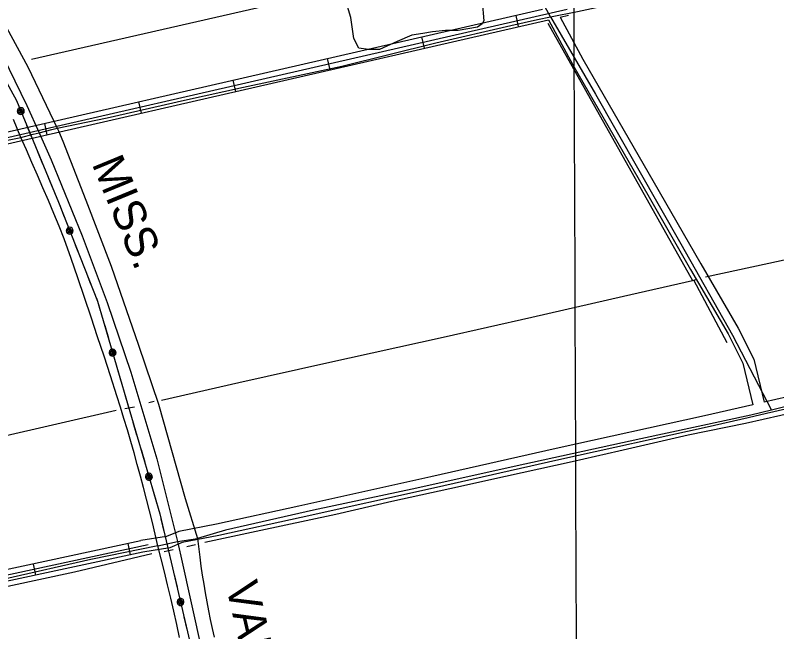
# Model space of a CAD drawing. Extents: x 3392644 to 3430565, y 576657 to 602123.
# Drawn here: x 3416383 to 3418352, y 588816 to 590409 of the extents above; entities that cross this region are included whole.
import ezdxf

# ---------------------------------------------------------------- set-up
doc = ezdxf.new("R2010")
doc.units = 0
for name, color, linetype in [('V-DTCH-CNTR', 7, 'Continuous'), ('V-GRID-MAJR', 7, 'Continuous'), ('V-RAIL-IDEN', 7, 'Continuous'), ('V-RAIL-TRAK', 7, 'Continuous'), ('V-ROAD-CNTR', 7, 'Continuous'), ('V-SITE-VEGE', 7, 'Continuous'), ('V-TOPO-SHOR', 7, 'Continuous'), ('V-UTIL-LINE', 7, 'Continuous')]:
    doc.layers.add(name, color=color, linetype=linetype)

msp = doc.modelspace()

# ---------------------------------------------------------------- linework, layer by layer
at = {"layer": 'V-DTCH-CNTR'}
for p, q in [((3416751.924, 589038.157), (3416802.573, 589049.001)), ((3416802.573, 589049.001), (3416854.21, 589057.238))]:
    msp.add_line(p, q, dxfattribs=at)
for points in [[(3416491.605, 590116.775), (3416620.816, 590143.532), (3416820.876, 590189.567), (3416973.508, 590222.931), (3417227.964, 590276.8470000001), (3417470.289, 590337.596), (3417664.788, 590381.71), (3417732.961, 590397.492), (3417766.504, 590404.1460000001), (3417837.039, 590418.138), (3418032.7090000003, 590461.1730000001), (3418235.963, 590511.853), (3418401.431, 590548.5650000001), (3418685.449, 590610.2000000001), (3418902.3880000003, 590657.762), (3419134.879, 590710.775), (3419369.647, 590763.316), (3419640.039, 590827.478), (3419543.482, 591021.51), (3419461.076, 591173.248), (3419330.748, 591406.505), (3419213.62, 591620.562), (3419101.41, 591830.308), (3419067.453, 591901.898)], [(3417766.504, 590404.1460000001), (3417681.237, 590559.925), (3417675.611, 590570.204), (3417541.109, 590808.931), (3417406.021, 591048.197), (3417273.464, 591280.797), (3417162.495, 591479.537), (3417026.426, 591721.203)], [(3416321.316, 590449.546), (3416415.936, 590275.182), (3416491.605, 590116.775), (3416494.9560000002, 590109.763), (3416506.207, 590083.149), (3416566.062, 589931.044), (3416631.211, 589759.976), (3416701.648, 589556.407), (3416753.62, 589403.979), (3416822.324, 589160.287), (3416854.21, 589057.238), (3416860.169, 589008.403), (3416863.458, 588985.302), (3416866.961, 588962.231), (3416870.676, 588939.193), (3416874.606, 588916.1900000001), (3416878.7490000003, 588893.226), (3416883.107, 588870.299), (3416887.674, 588847.414), (3416892.4560000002, 588824.5750000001), (3416897.449, 588801.779)], [(3417766.504, 590404.1460000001), (3417883.0100000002, 590204.818), (3418103.721, 589817.894), (3418236.98, 589581.938), (3418338.123, 589388.713)], [(3416808.378, 588801.046), (3416800.884, 588835.053), (3416793.198, 588869.017), (3416785.323, 588902.936), (3416777.258, 588936.812), (3416769.003, 588970.64), (3416760.559, 589004.422), (3416751.924, 589038.157), (3416744.9590000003, 589068.283), (3416737.793, 589098.3640000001), (3416730.427, 589128.394), (3416722.855, 589158.376), (3416715.085, 589188.306), (3416707.11, 589218.184), (3416698.9390000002, 589248.007), (3416690.5640000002, 589277.775), (3416681.989, 589307.487), (3416673.218, 589337.138), (3416664.2430000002, 589366.734), (3416655.072, 589396.2660000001), (3416645.705, 589425.735), (3416629.505, 589476.623), (3416613.086, 589527.442), (3416596.448, 589578.1900000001), (3416579.593, 589628.866), (3416562.519, 589679.468), (3416545.228, 589729.996), (3416527.718, 589780.448), (3416509.99, 589830.8250000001), (3416496.5470000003, 589863.853), (3416482.932, 589896.814), (3416469.145, 589929.7000000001), (3416455.186, 589962.515), (3416441.056, 589995.257), (3416426.757, 590027.925), (3416412.288, 590060.5160000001), (3416397.651, 590093.03), (3416388.234, 590115.9720000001), (3416378.6210000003, 590138.834)], [(3416220.878, 590052.077), (3416363.771, 590086.149), (3416397.667, 590092.992), (3416429.799, 590101.3250000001), (3416444.896, 590104.444), (3416477.7090000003, 590113.465), (3416491.605, 590116.775)], [(3419032.2430000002, 589545.584), (3418761.35, 589487.1950000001), (3418572.0500000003, 589446.526), (3418338.123, 589388.713), (3418284.453, 589375.4500000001), (3418000.406, 589314.11), (3417673.34, 589242.537), (3417421.772, 589187.046), (3417153.916, 589129.758), (3416927.0100000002, 589078.103), (3416854.21, 589057.238)], [(3416751.924, 589038.157), (3416579.065, 589002.831), (3416358.87, 588952.581), (3416176.576, 588913.485)]]:
    msp.add_lwpolyline(points, dxfattribs=at)
at = {"layer": 'V-GRID-MAJR'}
msp.add_spline([(3417859.292, 582120.98), (3417836.383, 588179.004), (3417813.4620000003, 594240.1140000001), (3417790.541, 600301.242), (3417790.529, 600304.306)], degree=3, dxfattribs=at)
at = {"layer": 'V-RAIL-TRAK'}
msp.add_lwpolyline([(3416192.597, 590596.707), (3416262.3540000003, 590474.978), (3416336.012, 590332.644), (3416413.347, 590175.192), (3416444.896, 590104.444), (3416475.932, 590034.8470000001), (3416556.703, 589838.446), (3416621.203, 589666.416), (3416682.344, 589486.919), (3416749.61, 589262.476), (3416802.573, 589049.001), (3416811.861, 589011.564), (3416866.719, 588762.179), (3416909.6350000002, 588565.4400000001), (3416972.856, 588276.088), (3417019.418, 588058.134), (3417070.958, 587822.036), (3417121.963, 587592.037), (3417123.169, 587586.438)], dxfattribs=at)
at = {"layer": 'V-ROAD-CNTR'}
for p, q in [((3417677.03260815, 590408.3251568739), (3417683.7365947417, 590379.0842153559)), ((3417433.3540955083, 590352.4602686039), (3417440.0580821, 590323.219327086)), ((3417189.676582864, 590296.596380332), (3417196.380569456, 590267.3544388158)), ((3416945.99907022, 590240.7314920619), (3416952.7020568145, 590211.490550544)), ((3416702.320557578, 590184.8676037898), (3416709.0245441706, 590155.6256622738)), ((3416458.643044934, 590129.0027155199), (3416465.3470315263, 590099.7617740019)), ((3416681.501599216, 589014.9209436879), (3416675.206611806, 589044.2528850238)), ((3416437.0700880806, 588962.45504862), (3416430.774100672, 588991.7869899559))]:
    msp.add_line(p, q, dxfattribs=at)
for points in [[(3417810.229341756, 590423.47212658), (3415682.2255977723, 589935.616102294)], [(3415687.339587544, 589952.17806917), (3417746.240469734, 590424.19212514)], [(3417791.6993788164, 590403.8341658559), (3417813.581335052, 590408.8511558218)], [(3417791.6993788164, 590403.8341658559), (3417850.6062610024, 590294.87238378), (3418048.1718658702, 589953.5170664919), (3418155.1476519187, 589766.3204408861), (3418252.269457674, 589599.964773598), (3418292.390377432, 589520.5039325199), (3418319.0123241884, 589408.803155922)], [(3415700.975560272, 589924.525124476), (3417761.3574395, 590396.8781797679)], [(3417761.3574395, 590396.8781797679), (3417824.42231337, 590280.22241308), (3418022.165917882, 589938.5610964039), (3418129.1697038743, 589751.3144708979), (3418225.9015104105, 589585.6288022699), (3418264.024434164, 589510.12395328), (3418289.7643826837, 589402.1241692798)], [(3418902.30015761, 589544.065885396), (3418797.492367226, 589520.04893343), (3418789.1113839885, 589518.952935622), (3418680.741600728, 589491.412990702), (3418319.0123241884, 589408.803155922)], [(3418918.49512522, 589516.9979395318), (3418802.80035661, 589490.4869925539), (3418794.7713726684, 589489.436994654), (3418687.777586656, 589462.2470490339), (3418325.3783114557, 589379.48421456)], [(3418289.7643826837, 589402.1241692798), (3418164.799632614, 589373.5852263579)], [(3418325.3783114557, 589379.48421456), (3418277.7164067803, 589368.59923633)], [(3418164.799632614, 589373.5852263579), (3417781.8403985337, 589288.9463956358), (3417457.867046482, 589216.383540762), (3417116.151729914, 589140.617692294), (3416903.753154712, 589094.1287852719), (3416806.330349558, 589075.053823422), (3416774.8074126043, 589061.9258496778), (3416707.925546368, 589051.2758709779)], [(3418277.7164067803, 589368.59923633), (3418171.4796192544, 589344.3372848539)], [(3418171.4796192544, 589344.3372848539), (3417788.2223857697, 589259.632454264), (3417464.39303343, 589187.1015993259), (3417122.6057170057, 589111.31975089), (3416909.8431425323, 589064.750844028), (3416815.0683320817, 589046.1958811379), (3416783.047396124, 589032.85990781), (3416713.4845352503, 589021.7859299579)], [(3416154.961652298, 588932.5911083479), (3416707.925546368, 589051.2758709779)], [(3416727.240507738, 589040.0798933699), (3416026.868908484, 588889.7501940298), (3415908.3611455, 588864.4192446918), (3415874.654212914, 588843.9242856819)], [(3416713.4845352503, 589021.7859299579), (3416158.6886309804, 588902.7029736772)]]:
    msp.add_lwpolyline(points, dxfattribs=at)
at = {"layer": 'V-SITE-VEGE'}
msp.add_lwpolyline([(3417590.6210000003, 590444.201), (3417594.771, 590394.385), (3417590.6210000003, 590386.083), (3417578.18, 590377.778), (3417528.401, 590369.478), (3417495.215, 590369.478), (3417462.029, 590365.324), (3417437.14, 590361.1730000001), (3417408.1040000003, 590357.024), (3417370.771, 590340.417), (3417325.1410000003, 590319.66), (3417296.105, 590319.66), (3417271.213, 590323.813), (3417258.77, 590348.719), (3417250.473, 590402.688), (3417233.878, 590460.806)], dxfattribs=at)
at = {"layer": 'V-TOPO-SHOR'}
for p, q in [((3416425.113, 590295.223), (3417625.339, 590568.775)), ((3417760.009, 590388.084), (3418133.759, 589723.706)), ((3418223.353, 589562.461), (3418137.732, 589724.612)), ((3416666.275, 589392.805), (3416691.4960000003, 589396.854)), ((3416728.839, 589407.983), (3416742.6240000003, 589411.184)), ((3416200.691, 589286.182), (3416644.275, 589388.138)), ((3416826.803, 589036.256), (3416849.555, 589040.954)), ((3416768.6750000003, 589022.955), (3416791.776, 589028.23))]:
    msp.add_line(p, q, dxfattribs=at)
for points in [[(3418167.393, 589732.625), (3418331.549, 589768.496), (3418552.419, 589816.71)], [(3416761.48, 589414.5920000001), (3416961.613, 589459.506), (3417189.1520000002, 589510.252), (3417489.19, 589576.959), (3417718.957, 589628.36), (3417955.919, 589683.254), (3418133.759, 589723.706), (3418137.732, 589724.612), (3418146.107, 589726.5160000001)], [(3416873.369, 589047.201), (3417006.468, 589075.813), (3417212.458, 589120.03), (3417356.654, 589153.236), (3417506.881, 589186.129), (3417650.572, 589217.811), (3417823.159, 589255.761), (3417943.514, 589283.284), (3418122.54, 589324.699), (3418271.184, 589354.89), (3418453.776, 589396.4500000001), (3418557.556, 589420.094), (3418755.02, 589465.841)], [(3416182.322, 588894.2440000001), (3416364.045, 588934.073), (3416536.295, 588971.068), (3416736.913, 589017.886)]]:
    msp.add_lwpolyline(points, dxfattribs=at)
at = {"layer": 'V-UTIL-LINE'}
for points in [[(3417186.864, 600288.879), (3415306.279, 597067.023), (3413990.571, 594815.96), (3413738.896, 594367.605), (3414019.188, 594062.863), (3414329.554, 593576.738), (3414657.473, 593049.707), (3414990.376, 592512.957), (3415312.202, 591995.327), (3416131.577, 590652.721), (3416386.4220000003, 590188.311), (3416495.035, 589926.031), (3416596.258, 589669.814), (3416757.253, 589120.116), (3417006.473, 588058.733), (3418156.504, 588313.401), (3418409.933, 588351.9130000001)], [(3416397.769, 590160.909), (3416399.329, 590163.327), (3416397.004, 590163.2390000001), (3416395.574, 590160.894), (3416396.987, 590158.33), (3416400.184, 590159.479), (3416402.0840000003, 590163.765), (3416398.957, 590166.669), (3416394.131, 590166.071), (3416392.169, 590161.934), (3416392.943, 590157.531), (3416397.204, 590155.27), (3416402.4050000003, 590157.074), (3416406.085, 590164.353), (3416404.134, 590167.273), (3416401.214, 590169.224), (3416397.77, 590169.909), (3416394.326, 590169.224), (3416391.406, 590167.274), (3416389.455, 590164.354), (3416388.769, 590160.91), (3416389.454, 590157.466), (3416391.4050000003, 590154.546), (3416394.324, 590152.595), (3416397.769, 590151.909), (3416401.213, 590152.594), (3416404.133, 590154.545), (3416406.0840000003, 590157.464), (3416406.769, 590160.909), (3416406.085, 590164.353)], [(3416412.701, 590124.853), (3416425.7090000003, 590093.4400000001)], [(3416441.0130000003, 590056.483), (3416454.022, 590025.0700000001)], [(3416469.326, 589988.1140000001), (3416482.3340000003, 589956.701)], [(3416497.535, 589919.703), (3416510.028, 589888.081)], [(3416524.348, 589851.834), (3416525.947, 589854.225), (3416523.6210000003, 589854.175), (3416522.153, 589851.854), (3416523.523, 589849.267), (3416526.739, 589850.3640000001), (3416528.7090000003, 589854.6190000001), (3416525.63, 589857.573), (3416520.794, 589857.054), (3416518.765, 589852.949), (3416519.467, 589848.534), (3416523.69, 589846.204), (3416528.921, 589847.9230000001), (3416532.718, 589855.1410000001), (3416530.816, 589858.0920000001), (3416527.928, 589860.091), (3416524.4960000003, 589860.832), (3416521.041, 589860.204), (3416518.09, 589858.302), (3416516.091, 589855.414), (3416515.349, 589851.982), (3416515.978, 589848.527), (3416517.88, 589845.5750000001), (3416520.767, 589843.576), (3416524.2, 589842.835), (3416527.6550000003, 589843.463), (3416530.606, 589845.366), (3416532.605, 589848.253), (3416533.347, 589851.686), (3416532.718, 589855.1410000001)], [(3416538.688, 589815.537), (3416551.181, 589783.915)], [(3416565.878, 589746.713), (3416578.3710000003, 589715.091)], [(3416593.068, 589677.89), (3416596.258, 589669.814), (3416603.3740000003, 589645.518)], [(3416614.617, 589607.131), (3416624.173, 589574.502)], [(3416635.127, 589537.099), (3416636.938, 589539.335), (3416634.617, 589539.498), (3416632.943, 589537.3200000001), (3416634.072, 589534.6190000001), (3416637.3740000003, 589535.4180000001), (3416639.724, 589539.475), (3416636.927, 589542.698), (3416632.065, 589542.622), (3416629.67, 589538.72), (3416629.966, 589534.259), (3416633.9590000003, 589531.553), (3416639.324, 589532.7880000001), (3416643.765, 589539.629), (3416642.139, 589542.742), (3416639.446, 589544.996), (3416636.095, 589546.047), (3416632.598, 589545.737), (3416629.485, 589544.111), (3416627.231, 589541.4180000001), (3416626.18, 589538.067), (3416626.49, 589534.5700000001), (3416628.116, 589531.457), (3416630.809, 589529.203), (3416634.159, 589528.152), (3416637.657, 589528.462), (3416640.77, 589530.088), (3416643.024, 589532.781), (3416644.075, 589536.131), (3416643.765, 589539.629)], [(3416646.097, 589499.6460000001), (3416655.653, 589467.017)], [(3416666.896, 589428.63), (3416676.452, 589396.001)], [(3416687.6950000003, 589357.6140000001), (3416697.251, 589324.985)], [(3416708.494, 589286.598), (3416718.0500000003, 589253.969)], [(3416729.005, 589216.5650000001), (3416730.816, 589218.801), (3416728.494, 589218.963), (3416726.821, 589216.786), (3416727.95, 589214.084), (3416731.252, 589214.884), (3416733.602, 589218.941), (3416730.805, 589222.164), (3416725.9420000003, 589222.088), (3416723.548, 589218.185), (3416723.843, 589213.725), (3416727.8370000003, 589211.019), (3416733.202, 589212.254), (3416737.642, 589219.095), (3416736.017, 589222.207), (3416733.324, 589224.461), (3416729.973, 589225.513), (3416726.475, 589225.202), (3416723.363, 589223.577), (3416721.109, 589220.884), (3416720.057, 589217.533), (3416720.3680000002, 589214.035), (3416721.9930000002, 589210.9230000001), (3416724.686, 589208.669), (3416728.037, 589207.617), (3416731.535, 589207.928), (3416734.647, 589209.553), (3416736.901, 589212.246), (3416737.953, 589215.5970000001), (3416737.642, 589219.095)], [(3416739.974, 589179.113), (3416749.5300000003, 589146.484)], [(3416760.116, 589107.9230000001), (3416767.8880000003, 589074.823)], [(3416777.031, 589035.883), (3416784.803, 589002.783)], [(3416793.947, 588963.8420000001), (3416801.719, 588930.742)], [(3416810.628, 588892.8), (3416812.558, 588894.934), (3416810.2490000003, 588895.2220000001), (3416808.4590000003, 588893.139), (3416809.44, 588890.38), (3416812.781, 588890.9990000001), (3416815.347, 588894.9230000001), (3416812.7290000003, 588898.2930000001), (3416807.87, 588898.481), (3416805.267, 588894.714), (3416805.3200000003, 588890.2440000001), (3416809.161, 588887.3250000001), (3416814.585, 588888.267), (3416819.39, 588894.857), (3416817.936, 588898.053), (3416815.369, 588900.4500000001), (3416812.08, 588901.682), (3416808.571, 588901.562), (3416805.375, 588900.107), (3416802.978, 588897.541), (3416801.7460000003, 588894.252), (3416801.867, 588890.743), (3416803.321, 588887.546), (3416805.8880000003, 588885.15), (3416809.176, 588883.9180000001), (3416812.686, 588884.0380000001), (3416815.882, 588885.492), (3416818.279, 588888.059), (3416819.5100000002, 588891.348), (3416819.39, 588894.857)], [(3416819.549, 588854.807), (3416827.321, 588821.707)]]:
    msp.add_lwpolyline(points, dxfattribs=at)

# ---------------------------------------------------------------- texts
at = {"layer": 'V-RAIL-IDEN'}
for s, rotation, p in [('MISS.', 292.42556670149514, (3416580.53349962, 590025.0708562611)), ('VALLEY)', 282.97998044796, (3416927.248642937, 588935.9527541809))]:
    msp.add_text(s, height=82.99983200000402, rotation=rotation, dxfattribs=at).set_placement(p)

doc.saveas('drawing.dxf')
